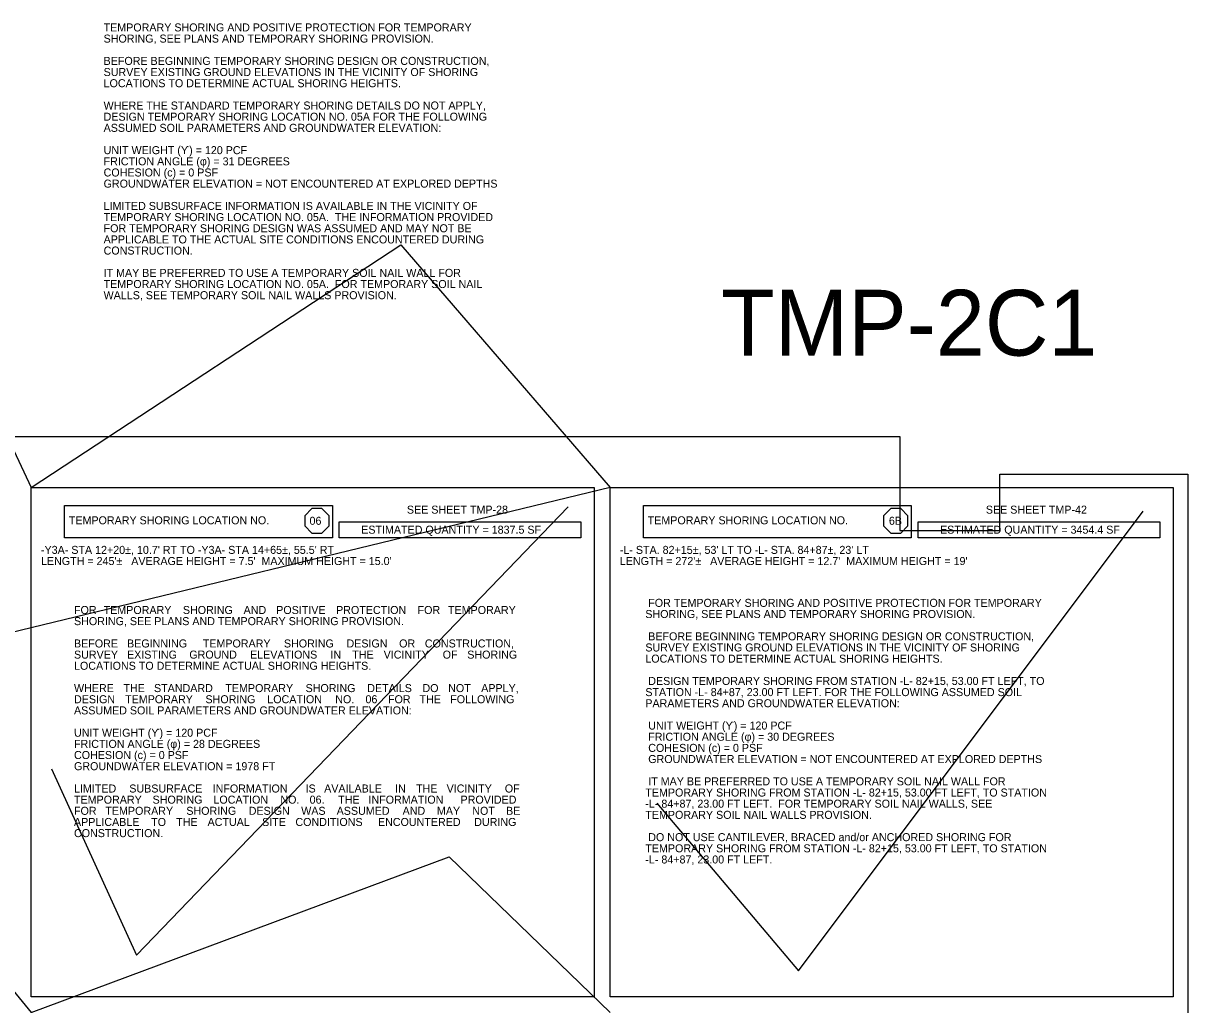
# Model space of a CAD drawing. Extents: x 2487012 to 2497594, y 369516 to 371986.
# Drawn here: x 2493067 to 2494058, y 370799 to 371634 of the extents above; entities that cross this region are included whole.
import ezdxf

# ---------------------------------------------------------------- set-up
doc = ezdxf.new("R2010")
doc.units = 0
for name, color, linetype in [('Scratch_Level_2', 7, 'Continuous'), ('Scratch_Level_6', 7, 'Continuous'), ('TC LABEL TEMP SHORING', 7, 'Continuous'), ('TC SHEET BORDER LINE THIN', 7, 'Continuous'), ('TC SHEET LAYOUT SHAPE', 7, 'Continuous'), ('TC SHEET TEXT', 7, 'Continuous')]:
    doc.layers.add(name, color=color, linetype=linetype)

msp = doc.modelspace()

# ---------------------------------------------------------------- linework, layer by layer
at = {"layer": 'Scratch_Level_2'}
for points in [[(2493090.87, 370999.66), (2493163.27, 370841.1), (2493530.94, 371222.61)], [(2493606.22, 370970.28), (2493726.9, 370827.82), (2494020.54, 371218.99)]]:
    msp.add_lwpolyline(points, dxfattribs=at)
at = {"layer": 'Scratch_Level_6'}
msp.add_lwpolyline([(2492568.34, 371282.27), (2492580.66, 371239.13), (2492982.22, 371433.43), (2493073.56, 371239.13), (2493388.33, 371445.42), (2493566.46, 371239.13), (2492395.04, 370955.22), (2492580.66, 370792.26), (2492940.95, 370953.89), (2493073.56, 370792.26), (2493429.6, 370924.58), (2493566.46, 370792.26)], dxfattribs=at)
at = {"layer": 'TC LABEL TEMP SHORING'}
for p, q in [((2493312.52, 371221.17), (2493306.43, 371215.01)), ((2493306.43, 371215.01), (2493306.43, 371206.28)), ((2493321.13, 371221.17), (2493312.52, 371221.17)), ((2493327.22, 371215.01), (2493321.13, 371221.17)), ((2493327.22, 371206.28), (2493327.22, 371215.01)), ((2493805.42, 371221.17), (2493799.33, 371215.01)), ((2493799.33, 371215.01), (2493799.33, 371206.28)), ((2493814.03, 371221.17), (2493805.42, 371221.17)), ((2493820.11, 371215.01), (2493814.03, 371221.17)), ((2493820.11, 371206.28), (2493820.11, 371215.01)), ((2493306.43, 371206.28), (2493312.52, 371200.12)), ((2493321.13, 371200.12), (2493327.22, 371206.28)), ((2493799.33, 371206.28), (2493805.42, 371200.12)), ((2493814.03, 371200.12), (2493820.11, 371206.28)), ((2493312.52, 371200.12), (2493321.13, 371200.12)), ((2493805.42, 371200.12), (2493814.03, 371200.12))]:
    msp.add_line(p, q, dxfattribs=at)
at = {"layer": 'TC SHEET BORDER LINE THIN'}
for points in [[(2493073.56, 371239.13), (2493553, 371239.13), (2493553, 370805.5), (2493073.56, 370805.5)], [(2493566.46, 371239.13), (2494045.9, 371239.13), (2494045.9, 370805.5), (2493566.46, 370805.5)], [(2493102.05, 371223.55), (2493330.1, 371223.55), (2493330.1, 371196.29), (2493102.05, 371196.29)], [(2493594.95, 371223.55), (2493823, 371223.55), (2493823, 371196.29), (2493594.95, 371196.29)], [(2493335.87, 371209.92), (2493541.65, 371209.92), (2493541.65, 371196.29), (2493335.87, 371196.29)], [(2493828.76, 371209.92), (2494034.54, 371209.92), (2494034.54, 371196.29), (2493828.76, 371196.29)]]:
    msp.add_lwpolyline(points, close=True, dxfattribs=at)
at = {"layer": 'TC SHEET LAYOUT SHAPE'}
msp.add_lwpolyline([(2492568.34, 370690.84), (2492568.34, 371000.16), (2492568.34, 371272.27), (2492578.34, 371282.27), (2493021.36, 371282.27), (2493492.34, 371282.27), (2493813.34, 371282.27), (2493813.34, 371202.27), (2493898.34, 371202.27), (2493898.34, 371250.27), (2494058.34, 371250.27), (2494058.34, 370915.3), (2494058.34, 370636.1), (2494058.34, 370384.77), (2493703.34, 370384.77), (2493703.34, 370242.27), (2493330.16, 370242.27), (2493160.7, 370242.27), (2492807.92, 370242.27), (2492568.34, 370242.27)], close=True, dxfattribs=at)

# ---------------------------------------------------------------- texts
at = {"layer": 'TC LABEL TEMP SHORING'}
for s, p in [('06', (2493310.57, 371207.28)), ('6B', (2493803.91, 371207.28))]:
    msp.add_text(s, height=6.814, dxfattribs=at).set_placement(p)
at = {"layer": 'TC SHEET BORDER LINE THIN'}
for s, height, p in [('TEMPORARY SHORING AND POSITIVE PROTECTION FOR TEMPORARY ', 6.8137, (2493135.22, 371627.11)), ('SHORING, SEE PLANS AND TEMPORARY SHORING PROVISION. ', 6.8137, (2493135.22, 371617.61)), ('BEFORE BEGINNING TEMPORARY SHORING DESIGN OR CONSTRUCTION, ', 6.8137, (2493135.22, 371598.62)), ('SURVEY EXISTING GROUND ELEVATIONS IN THE VICINITY OF SHORING ', 6.8137, (2493135.22, 371589.13)), ('LOCATIONS TO DETERMINE ACTUAL SHORING HEIGHTS. ', 6.8137, (2493135.22, 371579.63)), ('WHERE THE STANDARD TEMPORARY SHORING DETAILS DO NOT APPLY, ', 6.8137, (2493135.22, 371560.65)), ('DESIGN TEMPORARY SHORING LOCATION NO. 05A FOR THE FOLLOWING ', 6.8137, (2493135.22, 371551.15)), ('ASSUMED SOIL PARAMETERS AND GROUNDWATER ELEVATION: ', 6.8137, (2493135.22, 371541.66)), ('UNIT WEIGHT (ϒ) = 120 PCF ', 6.8137, (2493135.22, 371522.67)), ('FRICTION ANGLE (φ) = 31 DEGREES ', 6.8137, (2493135.22, 371513.17)), ('COHESION (c) = 0 PSF ', 6.8137, (2493135.22, 371503.68)), ('GROUNDWATER ELEVATION = NOT ENCOUNTERED AT EXPLORED DEPTHS ', 6.8137, (2493135.22, 371494.19)), ('LIMITED SUBSURFACE INFORMATION IS AVAILABLE IN THE VICINITY OF ', 6.8137, (2493135.22, 371475.2)), ('TEMPORARY SHORING LOCATION NO. 05A.  THE INFORMATION PROVIDED ', 6.8137, (2493135.22, 371465.7)), ('FOR TEMPORARY SHORING DESIGN WAS ASSUMED AND MAY NOT BE ', 6.8137, (2493135.22, 371456.21)), ('APPLICABLE TO THE ACTUAL SITE CONDITIONS ENCOUNTERED DURING ', 6.8137, (2493135.22, 371446.71)), ('CONSTRUCTION. ', 6.8137, (2493135.22, 371437.22)), ('IT MAY BE PREFERRED TO USE A TEMPORARY SOIL NAIL WALL FOR ', 6.8137, (2493135.22, 371418.23)), ('TEMPORARY SHORING LOCATION NO. 05A.  FOR TEMPORARY SOIL NAIL ', 6.8137, (2493135.22, 371408.74)), ('WALLS, SEE TEMPORARY SOIL NAIL WALLS PROVISION.', 6.8137, (2493135.22, 371399.24)), ('FOR TEMPORARY SHORING AND POSITIVE PROTECTION FOR TEMPORARY ', 6.8137, (2493598.98, 371137.44)), ('FOR ', 6.814, (2493110.02, 371131.36)), ('TEMPORARY ', 6.814, (2493135.26, 371131.36)), ('SHORING ', 6.814, (2493202.74, 371131.36)), ('AND ', 6.814, (2493254.43, 371131.36)), ('POSITIVE ', 6.814, (2493282.21, 371131.36)), ('PROTECTION ', 6.8137, (2493333.18, 371131.36)), ('FOR ', 6.814, (2493402.58, 371131.36)), ('TEMPORARY ', 6.814, (2493428.49, 371131.36)), ('SHORING, SEE PLANS AND TEMPORARY SHORING PROVISION.', 6.8137, (2493596.5, 371127.94)), ('SHORING, SEE PLANS AND TEMPORARY SHORING PROVISION.', 6.8137, (2493110.02, 371121.87)), ('BEFORE BEGINNING TEMPORARY SHORING DESIGN OR CONSTRUCTION, ', 6.8137, (2493598.98, 371108.95)), ('BEFORE ', 6.814, (2493110.02, 371102.88)), ('BEGINNING ', 6.814, (2493155.18, 371102.88)), ('TEMPORARY ', 6.814, (2493219.67, 371102.88)), ('SHORING ', 6.814, (2493288.75, 371102.88)), ('DESIGN ', 6.814, (2493342.03, 371102.88)), ('OR ', 6.814, (2493386.86, 371102.88)), ('CONSTRUCTION, ', 6.8137, (2493408.75, 371102.88)), ('SURVEY EXISTING GROUND ELEVATIONS IN THE VICINITY OF SHORING ', 6.8137, (2493596.5, 371099.46)), ('SURVEY ', 6.814, (2493110.02, 371093.39)), ('EXISTING ', 6.814, (2493155.16, 371093.39)), ('GROUND ', 6.814, (2493208.19, 371093.39)), ('ELEVATIONS ', 6.8137, (2493259.92, 371093.39)), ('IN ', 6.814, (2493328.4, 371093.39)), ('THE ', 6.814, (2493346.94, 371093.39)), ('VICINITY ', 6.814, (2493373.68, 371093.39)), ('OF ', 6.814, (2493423.95, 371093.39)), ('SHORING ', 6.814, (2493444.89, 371093.39)), ('LOCATIONS TO DETERMINE ACTUAL SHORING HEIGHTS.', 6.8137, (2493596.5, 371089.96)), ('LOCATIONS TO DETERMINE ACTUAL SHORING HEIGHTS.', 6.8137, (2493110.02, 371083.89)), ('DESIGN TEMPORARY SHORING FROM STATION -L- 82+15, 53.00 FT LEFT, TO ', 6.8137, (2493598.98, 371070.97)), ('WHERE ', 6.814, (2493110.02, 371064.9)), ('THE ', 6.814, (2493152.1, 371064.9)), ('STANDARD ', 6.814, (2493178.12, 371064.9)), ('TEMPORARY ', 6.814, (2493238.9, 371064.9)), ('SHORING ', 6.814, (2493307.21, 371064.9)), ('DETAILS ', 6.814, (2493359.73, 371064.9)), ('DO ', 6.814, (2493406.72, 371064.9)), ('NOT ', 6.814, (2493428.62, 371064.9)), ('APPLY, ', 6.814, (2493456.75, 371064.9)), ('STATION -L- 84+87, 23.00 FT LEFT. FOR THE FOLLOWING ASSUMED SOIL ', 6.8137, (2493596.5, 371061.48)), ('DESIGN ', 6.814, (2493110.02, 371055.41)), ('TEMPORARY ', 6.814, (2493153.53, 371055.41)), ('SHORING ', 6.814, (2493221.96, 371055.41)), ('LOCATION ', 6.814, (2493274.6, 371055.41)), ('NO. ', 6.814, (2493332.47, 371055.41)), ('06 ', 6.814, (2493358.2, 371055.41)), ('FOR ', 6.814, (2493377.39, 371055.41)), ('THE ', 6.814, (2493404.24, 371055.41)), ('FOLLOWING ', 6.814, (2493430.38, 371055.41)), ('PARAMETERS AND GROUNDWATER ELEVATION:', 6.8137, (2493596.5, 371051.99)), ('ASSUMED SOIL PARAMETERS AND GROUNDWATER ELEVATION:', 6.8137, (2493110.02, 371045.91)), ('UNIT WEIGHT (ϒ) = 120 PCF ', 6.8137, (2493110.02, 371026.92)), ('UNIT WEIGHT (ϒ) = 120 PCF', 6.8137, (2493598.98, 371033)), ('FRICTION ANGLE (φ) = 28 DEGREES ', 6.8137, (2493110.02, 371017.43)), ('FRICTION ANGLE (φ) = 30 DEGREES', 6.8137, (2493598.98, 371023.5)), ('COHESION (c) = 0 PSF ', 6.8137, (2493110.02, 371007.94)), ('COHESION (c) = 0 PSF', 6.8137, (2493598.98, 371014.01)), ('GROUNDWATER ELEVATION = 1978 FT', 6.8137, (2493110.02, 370998.44)), ('GROUNDWATER ELEVATION = NOT ENCOUNTERED AT EXPLORED DEPTHS', 6.8137, (2493598.98, 371004.51)), ('LIMITED ', 6.814, (2493110.02, 370979.45)), ('SUBSURFACE ', 6.8137, (2493157.08, 370979.45)), ('INFORMATION ', 6.8137, (2493228.08, 370979.45)), ('IS ', 6.814, (2493307.2, 370979.45)), ('AVAILABLE ', 6.814, (2493323.03, 370979.45)), ('IN ', 6.814, (2493383.46, 370979.45)), ('THE ', 6.814, (2493401.29, 370979.45)), ('VICINITY ', 6.814, (2493427.31, 370979.45)), ('OF ', 6.814, (2493476.86, 370979.45)), ('IT MAY BE PREFERRED TO USE A TEMPORARY SOIL NAIL WALL FOR ', 6.8137, (2493598.98, 370985.53)), ('TEMPORARY ', 6.814, (2493110.02, 370969.96)), ('SHORING ', 6.814, (2493176.93, 370969.96)), ('LOCATION ', 6.814, (2493228.73, 370969.96)), ('NO. ', 6.814, (2493285.76, 370969.96)), ('06. ', 6.814, (2493310.65, 370969.96)), (' THE ', 6.814, (2493332.38, 370969.96)), ('INFORMATION ', 6.8137, (2493360.77, 370969.96)), ('PROVIDED ', 6.814, (2493439.16, 370969.96)), ('TEMPORARY SHORING FROM STATION -L- 82+15, 53.00 FT LEFT, TO STATION ', 6.8137, (2493596.5, 370976.03)), ('FOR ', 6.814, (2493110.02, 370960.46)), ('TEMPORARY ', 6.814, (2493136.71, 370960.46)), ('SHORING ', 6.814, (2493205.64, 370960.46)), ('DESIGN ', 6.814, (2493258.78, 370960.46)), ('WAS ', 6.814, (2493303.47, 370960.46)), ('ASSUMED ', 6.814, (2493333.65, 370960.46)), ('AND ', 6.814, (2493389.82, 370960.46)), ('MAY ', 6.814, (2493419.05, 370960.46)), ('NOT ', 6.814, (2493449.16, 370960.46)), ('BE ', 6.814, (2493477.92, 370960.46)), ('-L- 84+87, 23.00 FT LEFT.  FOR TEMPORARY SOIL NAIL WALLS, SEE ', 6.8137, (2493596.5, 370966.54)), ('APPLICABLE ', 6.8137, (2493110.02, 370950.97)), ('TO ', 6.814, (2493175.72, 370950.97)), ('THE ', 6.814, (2493196.99, 370950.97)), ('ACTUAL ', 6.814, (2493223.75, 370950.97)), ('SITE ', 6.814, (2493270.16, 370950.97)), ('CONDITIONS ', 6.8137, (2493298.55, 370950.97)), ('ENCOUNTERED ', 6.8137, (2493368.85, 370950.97)), ('DURING ', 6.814, (2493450.8, 370950.97)), ('TEMPORARY SOIL NAIL WALLS PROVISION. ', 6.8137, (2493596.5, 370957.04)), ('CONSTRUCTION.', 6.8137, (2493110.02, 370941.48)), ('DO NOT USE CANTILEVER, BRACED and/or ANCHORED SHORING FOR ', 6.8137, (2493598.98, 370938.05)), ('TEMPORARY SHORING FROM STATION -L- 82+15, 53.00 FT LEFT, TO STATION ', 6.8137, (2493596.5, 370928.56)), ('-L- 84+87, 23.00 FT LEFT.', 6.8137, (2493596.5, 370919.06))]:
    msp.add_text(s, height=height, dxfattribs=at).set_placement(p)
at = {"layer": 'TC SHEET LAYOUT SHAPE'}
msp.add_text('TMP-2C1', height=55.996, rotation=0.00008, dxfattribs=at).set_placement((2493661.01, 371351.23))
at = {"layer": 'TC SHEET TEXT'}
for s, p in [('SEE SHEET TMP-28', (2493393.48, 371216.75)), ('SEE SHEET TMP-42', (2493886.45, 371216.75)), ('TEMPORARY SHORING LOCATION NO.', (2493105.62, 371207.68)), ('TEMPORARY SHORING LOCATION NO.', (2493598.51, 371207.68)), ('ESTIMATED QUANTITY = 1837.5 SF', (2493354.57, 371199.7)), ('ESTIMATED QUANTITY = 3454.4 SF', (2493847.46, 371199.7)), ("-Y3A- STA 12+20±, 10.7' RT TO -Y3A- STA 14+65±, 55.5' RT", (2493081.9, 371182.51)), ("-L- STA. 82+15±, 53' LT TO -L- STA. 84+87±, 23' LT", (2493574.79, 371182.51)), ("LENGTH = 245'±   AVERAGE HEIGHT = 7.5'  MAXIMUM HEIGHT = 15.0'", (2493081.9, 371173.02)), ("LENGTH = 272'±   AVERAGE HEIGHT = 12.7'  MAXIMUM HEIGHT = 19'", (2493574.79, 371173.02))]:
    msp.add_text(s, height=6.8137, dxfattribs=at).set_placement(p)

doc.saveas('drawing.dxf')
